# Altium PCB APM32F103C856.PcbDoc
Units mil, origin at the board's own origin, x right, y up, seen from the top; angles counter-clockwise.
Board outline 2110.03 x 910.03 mil, 2 copper layers (Top Layer, Bottom Layer); 23 components, 48 nets, 151 pads, 35 vias.
Unrouted connection lines stored in the file: 7.
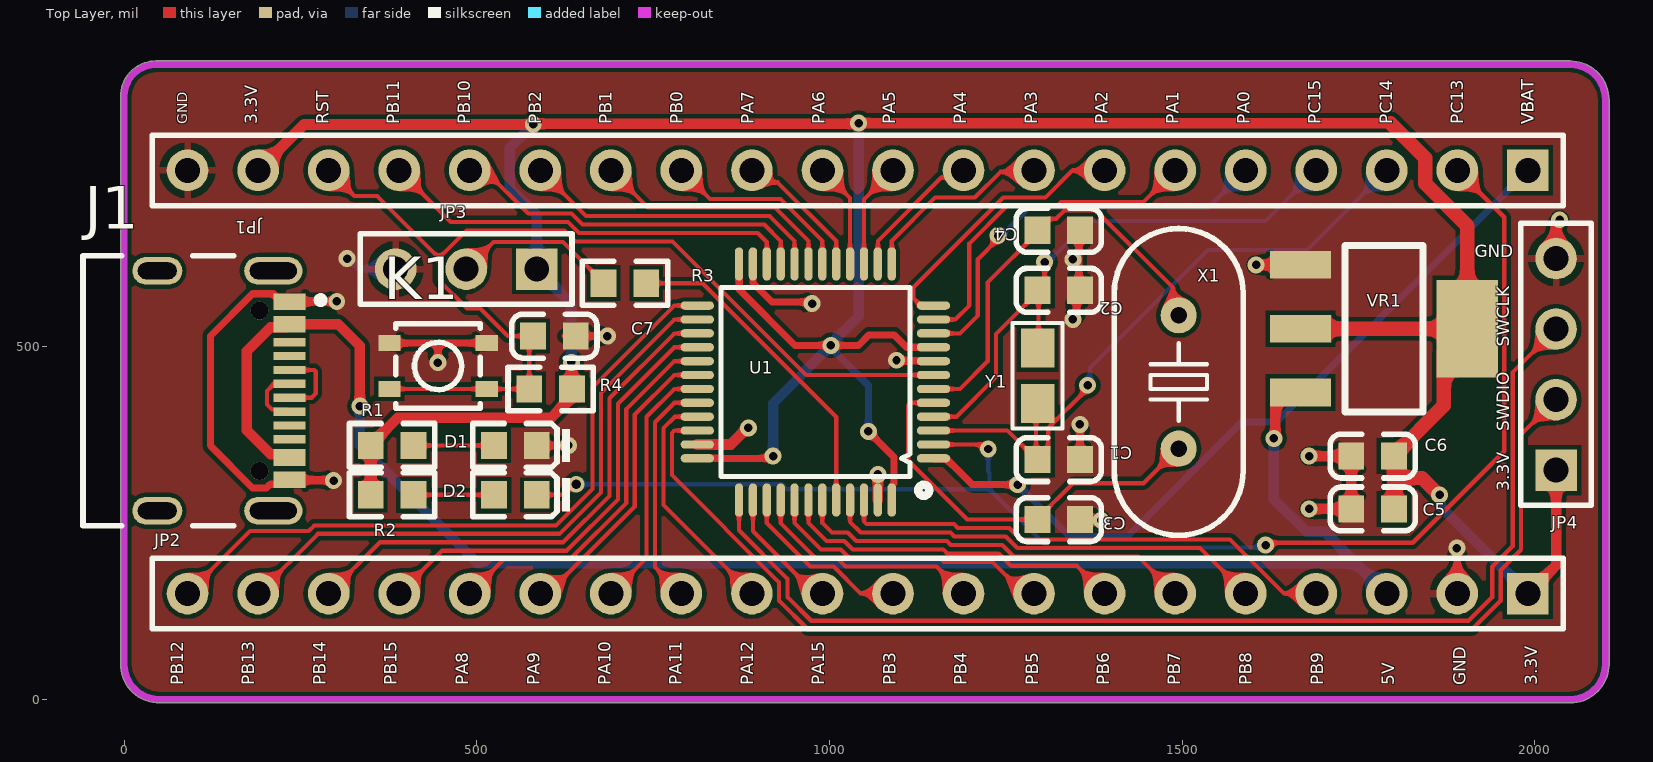
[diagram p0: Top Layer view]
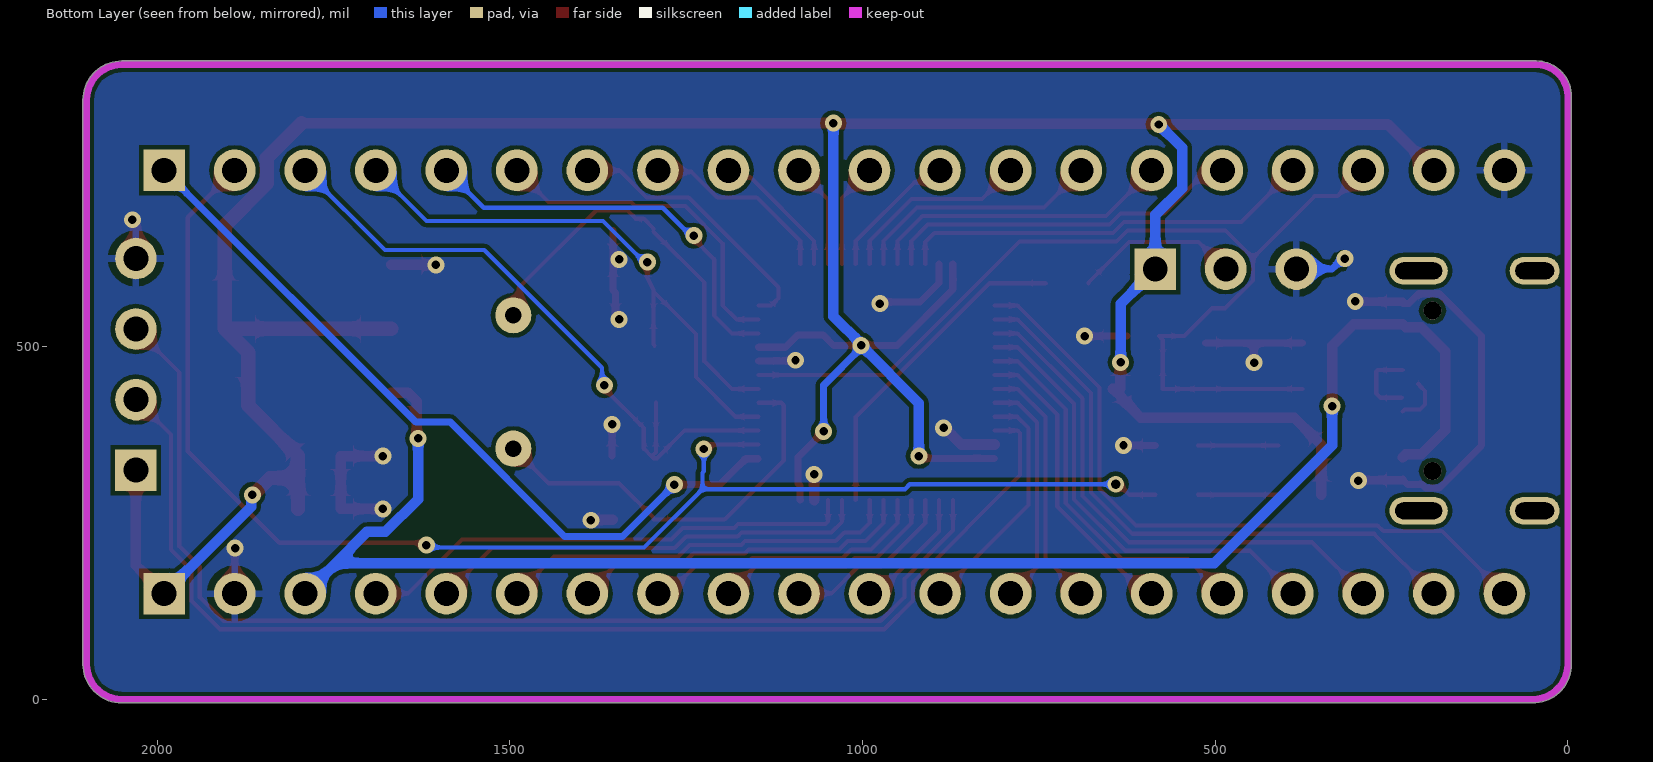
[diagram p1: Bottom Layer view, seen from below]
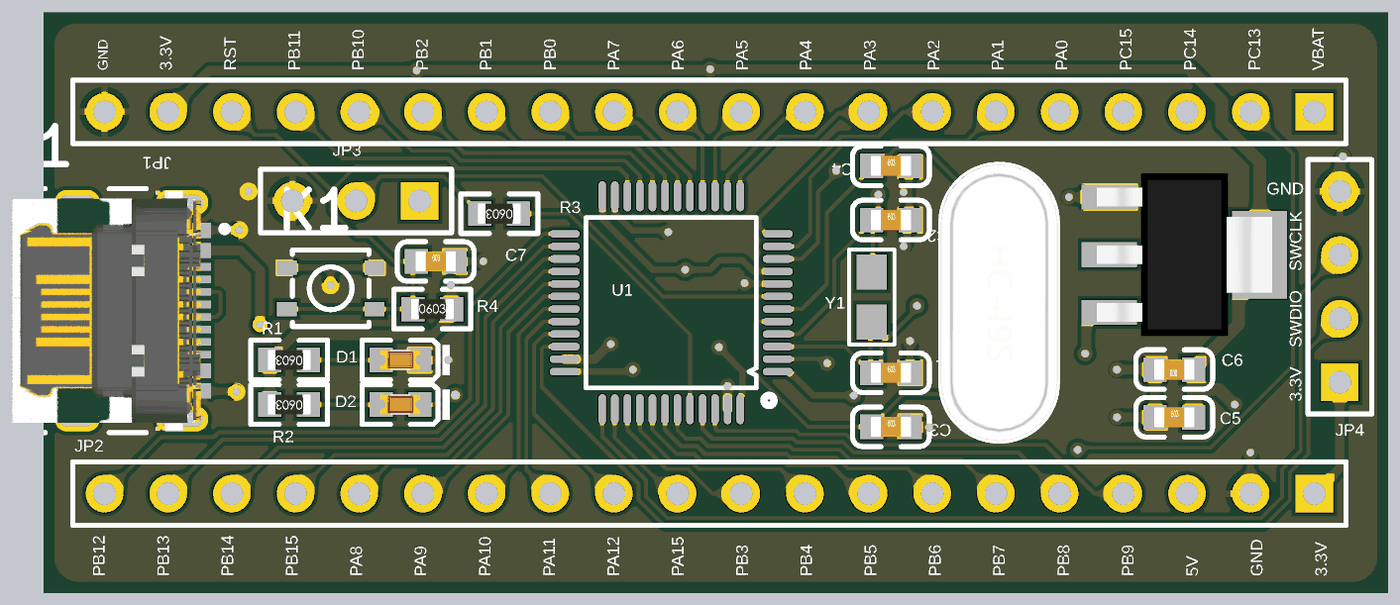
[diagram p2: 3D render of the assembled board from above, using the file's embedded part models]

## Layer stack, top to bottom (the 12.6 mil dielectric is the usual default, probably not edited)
Top Solder: solder mask 0.4, Solder Resist, Dk 3.5
Top Layer: signal copper 1.4
Dielectric 1: dielectric 12.6, FR-4, Dk 4.8
Bottom Layer: signal copper 1.4
Bottom Solder: solder mask 0.4, Solder Resist, Dk 3.5

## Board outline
-5.02,50 -5.02,855 cw(c45,855) 45,905.02 cw(c45,900) 45.04,905.01 2050,905.02 cw(c2050,850) 2105.01,850 2105.01,50 cw(c2050,50) 2050,-5.02 52.5,-5.02 cw(c52.5,0) 52.46,-5.02 50,-5.02 cw(c50,50)

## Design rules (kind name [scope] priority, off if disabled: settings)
Clearance poly [InPolygon] p1: gap=6 ignorepadtopadclearanceinfootprint=TRUE
Clearance [All] p2: gap=6 ignorepadtopadclearanceinfootprint=TRUE
ComponentClearance [All] p1: gap=0 collisioncheckmode=3 verticalgap=0 showdistances=FALSE
HoleToHoleClearance [All] p1: gap=0 allowstackedmicrovias=TRUE
MinimumSolderMaskSliver [All] p1: minsoldermaskwidth=0
PlaneConnect [All] p1: pad.planeconnectstyle=Relief pad.reliefexpansion=20 pad.reliefentries=4 pad.reliefconductorwidth=10 pad.reliefairgap=10 via.planeconnectstyle=Direct via.reliefexpansion=20 via.reliefentries=4 via.reliefconductorwidth=10 via.reliefairgap=10
PolygonConnect [All] p1: thpad.connectstyle=Relief thpad.reliefconductorwidth=10 thpad.reliefentries=4 thpad.polygonreliefangle="90 Angle" thpad.airgapwidth=10 smdpad.connectstyle=Direct smdpad.reliefconductorwidth=10 smdpad.reliefentries=4 smdpad.polygonreliefangle="90 Angle" smdpad.airgapwidth=10 via.connectstyle=Direct via.reliefconductorwidth=10 via.reliefentries=4 via.polygonreliefangle="90 Angle" via.airgapwidth=10
RoutingVias [All] p1: holewidth=12 width=24 viastyle="Through Hole" minholewidth=12 minwidth=24 maxholewidth=12 maxwidth=24
SilkToSilkClearance [All] p1: silktosilkclearance=0
SilkToSolderMaskClearance [IsPad] p1: minsilkscreentomaskgap=0 clearancetoexposedcopper=TRUE
SolderMaskExpansion [All] p1: expansion=2 istentingtop=FALSE useseparateexpansions=TRUE expansionbottom=2 istentingbottom=FALSE
Width Width_1 [InNetClass('POWER')] p1: maxlimit=30 minlimit=10 preferedwidth=15
Width [InNetClass('All Nets')] p2: maxlimit=30 minlimit=6 preferedwidth=6
24 further rules are at their usual default settings.

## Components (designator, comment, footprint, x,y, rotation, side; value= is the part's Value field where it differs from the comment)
C1 "22PF" 0603_C 1325,340 r0 top
C2 "22PF" 0603_C 1325,580 r0 top
C3 "22PF" 0603_C 1325,255 r0 top
C4 "22PF" 0603_C 1325,665 r0 top
C5 "100pF (101) 5% 50V" 0603_C 1770,270 r0 top
C6 "100pF (101) 5% 50V" 0603_C 1770,345 r180 top
C7 "100nF (104) 10% 50V" 0603_C 610,515 r0 top
D1 "红灯 0603" 0603_LED_S1 554.69,360 r180 top
D2 "绿灯 0603" 0603_LED_S1 554.69,290 r180 top
J1 "USB4105-GF-A" FP-USB4105-GF-A-MFG 92.95,437.51 r270 top locked
JP1 "HEADER 20" HDR1X20 1990,750 r180 top locked
JP2 "HEADER 20" HDR1X20 1990,150 r180 top locked
JP3 "HEADER 3" HDR1X3 585,610 r180 top
JP4 "4 HEADER" HDR1X4 2030,325 r90 top
K1 "GT-TS171E-H014-L1" SW-SMD_4P-L3.0-W2.8-P1.65-TL_GT-TS171A-H014-L1 445.13,472.64 r180 top
R1 "4.7KΩ (4701) ±1%" 0603_R 380,360 r180 top
R2 "4.7KΩ (4701) ±1%" 0603_R 380,290 r180 top
R3 "10KΩ (1002) ±1%" 0603_R 710,590 r180 top
R4 "10KΩ (1002) ±1%" 0603_R 604.68,440 r0 top
U1 "IC_APM32F103C8T6_1040100292" LQFP48 980,450 r180 top locked
VR1 "AMS1117-3.3" SOT-223 1786.03,525.5 r180 top
X1 "8MHz" "OSC HC-49S" 1495,450 r270 top
Y1 "CRYSTAL" 3215 1295.01,459.03 r270 top value=32.768KHZ

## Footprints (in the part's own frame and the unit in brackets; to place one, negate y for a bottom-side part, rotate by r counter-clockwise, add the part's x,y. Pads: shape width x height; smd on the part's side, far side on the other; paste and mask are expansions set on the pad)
0603_C [mm]
  rect 0.93x0.98 smd paste+0: 1(-0.77,0)
  rect 0.93x0.98 smd: 2(0.77,0)
  silkscreen extent -1.53,-0.79 1.54,0.79, body extent -0.8,-0.4 0.8,0.4, height 0.3
0603_LED_S1 [mm]
  rect 0.93x0.98 smd: A(0.77,0) K(-0.77,0)
  silkscreen extent -1.98,-0.79 1.54,0.79, body extent -0.8,-0.4 0.8,0.4, height 0.6
0603_R [mm]
  rect 0.93x0.98 smd: 1(-0.77,0) 2(0.77,0)
  silkscreen extent -1.53,-0.79 1.53,0.79, body extent -0.85,-0.4 0.85,0.4, height 0.56
3215 [mm]
  rect 1.4x1.2 smd mask+0.05: 1(-1,0) 2(1,0)
  silkscreen extent -1.9,-0.9 1.9,0.9
FP-USB4105-GF-A-MFG [mm]
  rrect100% 1x2.1 hole 1.7 slot 0.6 at 0 deg paste-1000 mask+0: 1(-4.32,3.015) 2(4.32,3.015)
  rrect100% 1x1.8 hole 1.4 slot 0.6 at 0 deg paste-1000 mask+0: 3(-4.32,-1.165) 4(4.32,-1.165)
  rect 0.6x1.15 smd paste+0 mask+0: A1-B12(-3.2,3.59) A4-B9(-2.4,3.59) B1-A12(3.2,3.59) B4-A9(2.4,3.59)
  rect 0.3x1.15 smd paste+0 mask+0: A5(-1.25,3.59) A6(-0.25,3.59) A7(0.25,3.59) A8(1.25,3.59) B5(1.75,3.59) B6(0.75,3.59) B7(-0.75,3.59) B8(-1.75,3.59)
  round 0.65 hole 0.65 unplated paste-1000 mask+0: ""(-2.89,2.515) ""(2.89,2.515)
  silkscreen extent -4.86,-3.84 4.86,4.84, body extent -4.96,-3.94 4.96,4.27, height 0.25
HDR1X3 [mm] "Connector; Header; 3 Position"
  rect 1.5x1.5 hole 0.9: 1(0,0)
  round 1.5 hole 0.9: 2(2.54,0) 3(5.08,0)
  silkscreen extent -1.27,-1.27 6.35,1.27
HDR1X4 [mm] "Connector; Header; 4 Position"
  rect 1.5x1.5 hole 0.9: 1(0,0)
  round 1.5 hole 0.9: 2(2.54,0) 3(5.08,0) 4(7.62,0)
  silkscreen extent -1.27,-1.27 8.89,1.27
HDR1X20 [mm] "Connector; Header; 20 Position"
  rect 1.5x1.5 hole 0.9: 1(0,0)
  round 1.5 hole 0.9: 2(2.54,0) 3(5.08,0) 4(7.62,0) 5(10.16,0) 6(12.7,0) 7(15.24,0) 8(17.78,0) 9(20.32,0) 10(22.86,0) 11(25.4,0) 12(27.94,0) 13(30.48,0) 14(33.02,0) 15(35.56,0) 16(38.1,0) 17(40.64,0) 18(43.18,0) 19(45.72,0) 20(48.26,0)
  silkscreen extent -1.27,-1.27 49.53,1.27
LQFP48 [mm]
  oval 1.2x0.3 smd: 1(-4.25,2.75) 2(-4.25,2.25) 3(-4.25,1.75) 4(-4.25,1.25) 5(-4.25,0.75) 6(-4.25,0.25) 7(-4.25,-0.25) 8(-4.25,-0.75) 9(-4.25,-1.25) 10(-4.25,-1.75) 11(-4.25,-2.25) 12(-4.25,-2.75) 25(4.25,-2.75) 26(4.25,-2.25) 27(4.25,-1.75) 28(4.25,-1.25) 29(4.25,-0.75) 30(4.25,-0.25) 31(4.25,0.25) 32(4.25,0.75) 33(4.25,1.25) 34(4.25,1.75) 35(4.25,2.25) 36(4.25,2.75)
  oval 0.3x1.2 smd: 13(-2.75,-4.25) 14(-2.25,-4.25) 15(-1.75,-4.25) 16(-1.25,-4.25) 17(-0.75,-4.25) 18(-0.25,-4.25) 19(0.25,-4.25) 20(0.75,-4.25) 21(1.25,-4.25) 22(1.75,-4.25) 23(2.25,-4.25) 24(2.75,-4.25) 37(2.75,4.25) 38(2.25,4.25) 39(1.75,4.25) 40(1.25,4.25) 41(0.75,4.25) 42(0.25,4.25) 43(-0.25,4.25) 44(-0.75,4.25) 45(-1.25,4.25) 46(-1.75,4.25) 47(-2.25,4.25) 48(-2.75,4.25)
  silkscreen extent -4.1,-3.4 3.4,4.1
"OSC HC-49S" [mm] "SMD, 2-Leads, Body 5x11.7mm"
  round 1.3 hole 0.6: 1(-2.4,0) 2(2.4,0)
  silkscreen extent -5.52,-2.32 5.52,2.33, body extent -5.52,-2.32 5.53,2.33, height 4.13
SOT-223 [mm]
  rect 2.2x1 smd: 1(3,-2.3) 2(3,0) 3(3,2.3)
  rect 2.2x3.5 smd: 2(-3,0)
  silkscreen extent -1.4,-3 1.4,3, body extent -3.49,-3.24 3.49,3.24, height 1.64
SW-SMD_4P-L3.0-W2.8-P1.65-TL_GT-TS171A-H014-L1 [mm]
  rect 0.8x0.575 smd: 1(-1.75,0.825) 2(-1.75,-0.825) 3(1.75,0.825) 4(1.75,-0.825)
  silkscreen extent -1.52,-1.52 1.52,1.52

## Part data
C1 C2 C3 C4 C5 C6: library part "0603 100pF (101) 5% 50V", "贴片电容", Package=0603, SuppliersPartNumber=C14858
C7: library part "0603 100nF (104) 10% 50V", "贴片电容", Package=0603, SuppliersPartNumber=C14663
D1: library part "0603 红灯", "发光二极管", Package=0603, SuppliersPartNumber=C2286
D2: library part "0603 绿灯", "发光二极管", Package=0603, SuppliersPartNumber=C72043
J1: library part CMP-245163-000001-1, "CONN RCPT USB2.0 TYPEC 5A", Current Rating=5/6.25/1.25/0.25A, Manufacturer=GCT, Package=0, Temperature="-40°C to +85°C", Temperature Range High=+85°C, Temperature Range Low=-40°C, Voltage Rating=20V
JP4: "4 Pin Header"
K1: BOM_JLCPCB Part Class="Extended Part", BOM_Manufacturer=G-Switch
R1 R2: library part "0603 4.7KΩ (4701) 1%", "贴片电阻", Package=0603, SuppliersPartNumber=C23162
R3 R4: library part "0603 10KΩ (1002) 1%", "贴片电阻", Package=0603, SuppliersPartNumber=C25804
VR1: library part "SOT-223 AMS1117-3.3", "低压差线性稳压(LDO)", Package=SOT-223, SuppliersPartNumber=C6186
X1: library part XTAL-2P, "2脚无源脚晶振"
Y1: "XTAL 32.768KHZ 7PF 20PPM -- SMT"

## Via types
v1: diameter 24, hole 12, Top Layer to Bottom Layer, tented both sides, 29 vias
v2: diameter 24, hole 12, Top Layer to Bottom Layer, 5 vias
v3: diameter 24, hole 14, Top Layer to Bottom Layer, tented both sides, 1 vias

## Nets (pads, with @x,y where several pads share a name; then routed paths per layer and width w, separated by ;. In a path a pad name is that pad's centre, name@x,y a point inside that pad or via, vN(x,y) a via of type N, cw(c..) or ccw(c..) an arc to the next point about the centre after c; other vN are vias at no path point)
BOOT0: R3.1 U1.44 | length 465.4
  Top Layer w6: R3.1 819.75,590 1009.53,400.22 U1.44
DN: J1.A7 J1.B7 | length 108.3
  Top Layer w6: J1.B7 269.64,467.03 271.8,464.87 271.8,433.59 265.92,427.71 J1.A7@235.6,427.71
DP: J1.A6 J1.B6 | length 69.1
  Top Layer w6: J1.A6@212.59,447.18 212.53,447.18 202.65,437.3 202.65,418.03 209.79,410.88 231.38,410.88 J1.B6
GND: C1.2 C2.2 C3.2 C4.2 C5.1 C6.2 C7.2 D1.K J1.A1-B12 J1.B1-A12 JP1.20 JP2.2 JP3.3 JP4.4 K1.2 K1.4 U1.8 U1.23 U1.35 U1.47 VR1.1 | length 1799.1
  Top Layer w10: J1.A1-B12@233.67,561.4 225.55,561.4 211.87,575.08 182.11,575.08 122.4,515.38 122.4,359.63 182.11,299.93 201.82,299.93 206.6,304.71 227.47,304.71 J1.B1-A12 ; K1.4 445.13,505.12 ; v2(444.93,477.36) 445.13,477.56 445.13,505.12 ; K1.2 445.13,505.12 ; D1.K v1(630,360) ; C7.2@625.32,515 v1(685,515) ; U1.23 891.77,616.97 891.77,590.2 918.47,563.5 972.87,563.5 v1(975.27,561.09) ; v1(1095,480.84) 1095.96,479.88 1146.97,479.88 U1.8 ; v1(1345,538.66) 1346.59,538.66 1350.37,542.44 1350.37,576.82 1353.54,580 v1@1353.54,623.66 ; v1(1345,623.66) v1@1353.54,623.66 ; C4.2@1353.54,665 v1@1353.54,623.66 ; C1.2@1355,345 v1(1355,390) ; v1(1889.47,214.47) 1889.73,214.2 1889.73,150.27 JP2.2
  Top Layer w12: J1.B1-A12 235.02,310.79 296.41,310.79 v2(297.15,310.05) ; J1.A1-B12 234.71,563.91 296.9,563.91 v2@297.73,564.74
  Top Layer w15: U1.35 859.79,361.42 883.37,385 v1(885,385) ; U1.47 U1.47 1068.64,318.94 v1(1068.69,319) ; C3.2@1354.04,254.5 1384.5,254.5 v1(1385,254) ; v1(1604.66,616.05) VR1.1 ; v1(1680,270) C5.1 C6.2 v1(1680,345) ; JP4.4 2030,672.56 2035,677.56 v1(2035,680)
  Bottom Layer w10: v2@318.21,626.1 318.7,626.1 334.44,610.36 384.64,610.36 JP3.3
  other v2: 301.45,564.33 316.15,624.86
NetC3_1: C3.1 U1.5 X1.2 | length 574.7
  Top Layer w6: U1.5 1115.18,420.47 1111.67,416.96 1111.67,338.59 1195.25,255 C3.1@1296.46,255 ; C3.1@1296.46,256.97 1296.46,257.76 1345.19,306.49 1445.08,306.49 1494.11,355.51 X1.2
NetC4_1: C4.1 U1.6 X1.1 | length 596.6
  Top Layer w6: U1.6 1184.99,440.16 1224.2,479.37 1224.2,590.86 1296.37,663.03 C4.1@1296.46,663.03 ; C4.1@1296.46,666.97 1296.46,667.76 1309.99,681.29 1321.28,681.29 1333.28,693.29 1377.35,693.29 1486.84,583.8 1486.84,552.65 X1.1
NetD1_A: D1.A R1.1 | length 114.1
  Top Layer w6: R1.1 D1.A
NetD2_A: D2.A R2.1 | length 114.1
  Top Layer w6: R2.1 D2.A
NetJP3_2: JP3.2 R3.2 | length 235.5
  Top Layer w6: JP3.2 523.53,648.53 622.14,648.53 679.68,590.98 R3.2
PA0: JP1.5 U1.10 | length 593.2
  Top Layer w6: U1.10 1184.99,518.9 1210.26,544.17 1210.26,624.05 1238.97,652.76 v1(1238.97,657.5)
  Bottom Layer w6: v1@1235.25,653.78 1239.99,653.78 1283.15,696.94 1536.94,696.94 JP1.5
PA1: JP1.6 U1.11 | length 481.7
  Top Layer w6: U1.11 1178.18,538.58 1198.26,558.66 1198.26,646.49 1251.24,699.47 1322.49,699.47 1328.31,705.29 1445.29,705.29 JP1.6
PA2: JP1.7 U1.12 | length 387.7
  Top Layer w6: U1.12 1129.6,558.27 1119.06,568.81 1119.06,584.27 1246.27,711.47 1305.96,711.47 1344.12,749.63 1389.63,749.63 JP1.7
PA3: JP1.8 U1.13 | length 275.8
  Top Layer w6: U1.13 1088.27,649.94 1149.8,711.47 1205.96,711.47 1242.4,747.91 1287.91,747.91 JP1.8
PA4: JP1.9 U1.14 | length 195.5
  Top Layer w6: U1.14 1068.58,649.94 1158.49,739.85 1179.85,739.85 JP1.9
PA5: JP1.10 U1.15 | length 149.7
  Top Layer w6: U1.15 1048.9,708.9 JP1.10
PA6: JP1.11 U1.16 | length 148.9
  Top Layer w6: JP1.11 1029.21,710.79 U1.16
PA7: JP1.12 U1.17 | length 193.6
  Top Layer w6: JP1.12 907.02,732.98 926.49,732.98 1009.53,649.94 U1.17
PA8: JP2.16 U1.29 | length 537.1
  Top Layer w6: JP2.16 538.71,198.71 632.29,198.71 712,278.42 712,411.47 780.06,479.53 U1.29
PA9: JP2.15 U1.30 | length 427.4
  Top Layer w6: JP2.15 600.55,150 724,273.45 724,403.78 780.06,459.84 U1.30
PA10: JP2.14 U1.31 | length 360.1
  Top Layer w6: JP2.14 740.54,200.54 740.54,400.65 780.06,440.16 U1.31
PA11: JP2.13 U1.32 | length 330
  Top Layer w6: JP2.13 752.54,187.46 752.54,392.96 780.06,420.47 U1.32
PA12: JP2.12 U1.33 | length 341.4
  Top Layer w6: U1.33 780.79,400.79 764.54,384.54 764.54,275.46 JP2.12
PA15: JP2.11 U1.38 | length 179.5
  Top Layer w6: U1.38 891.42,238.3 979.72,150 JP2.11
PB0: JP1.13 U1.18 | length 273.9
  Top Layer w6: JP1.13 830.75,709.25 930.53,709.25 989.84,649.94 U1.18
PB1: JP1.14 U1.19 | length 354.2
  Top Layer w6: JP1.14 742.75,697.25 922.85,697.25 970.16,649.94 U1.19
PB2: JP1.15 U1.20 | length 434.5
  Top Layer w6: JP1.15 654.75,685.25 915.16,685.25 950.47,649.94 U1.20
PB3: JP2.10 U1.39 | length 253
  Top Layer w6: U1.39 911.1,250.06 972.63,188.53 1005.96,188.53 1044.12,150.37 1089.63,150.37 JP2.10
PB4: JP2.9 U1.40 | length 333.3
  Top Layer w6: U1.40 930.79,250.06 980.32,200.53 1010.93,200.53 1022.93,188.53 1151.47,188.53 JP2.9
PB5: JP2.8 U1.41 | length 413.6
  Top Layer w6: U1.41 950.47,250.06 988,212.53 1015.9,212.53 1027.9,200.53 1156.44,200.53 1161.97,195 1230.85,195 1275.85,150 JP2.8
PB6: JP2.7 U1.42 | length 493.9
  Top Layer w6: U1.42 970.16,250.06 995.69,224.53 1020.87,224.53 1032.87,212.53 1161.41,212.53 1166.94,207 1239.99,207 1257.66,189.33 1350.67,189.33 JP2.7
PB7: JP2.6 U1.43 | length 574.2
  Top Layer w6: U1.43 989.84,250.06 1003.37,236.53 1025.84,236.53 1037.84,224.53 1166.38,224.53 1171.91,219 1244.96,219 1261.25,202.71 1437.29,202.71 JP2.6
PB8: JP2.5 U1.45 | length 633.9
  Top Layer w6: U1.45 1029.21,251.71 1044.39,236.53 1171.35,236.53 1176.88,231 1249.93,231 1266.22,214.71 1525.29,214.71 JP2.5
PB9: JP2.4 U1.46 | length 714
  Top Layer w6: U1.46 1048.9,252.04 1052.41,248.53 1176.32,248.53 1181.85,243 1254.9,243 1271.19,226.71 1567.78,226.71 1644.12,150.37 1689.63,150.37 JP2.4
PB10: JP1.16 U1.21 | length 514.9
  Top Layer w6: JP1.16 511.85,750 573.03,688.82 634.21,688.82 649.78,673.25 907.48,673.25 930.79,649.94 U1.21
PB11: JP1.17 U1.22 | length 594.3
  Top Layer w6: JP1.17 463.18,676.82 629.24,676.82 644.81,661.25 898.24,661.25 911.1,648.39 U1.22
PB12: JP2.20 U1.25 | length 976.1
  Top Layer w6: JP2.20 178.74,238.74 261.77,238.74 269.74,246.71 612.41,246.71 664,298.3 664,442.21 780.06,558.27 U1.25
PB13: JP2.19 U1.26 | length 866.3
  Top Layer w6: JP2.19 274.71,234.71 617.38,234.71 676,293.33 676,434.52 780.06,538.58 U1.26
PB14: JP2.18 U1.27 | length 756.6
  Top Layer w6: JP2.18 362.71,222.71 622.35,222.71 688,288.36 688,426.84 780.06,518.9 U1.27
PB15: JP2.17 U1.28 | length 646.9
  Top Layer w6: JP2.17 450.71,210.71 627.32,210.71 700,283.39 700,419.15 780.06,499.21 U1.28
PC13: D2.K JP1.2 U1.2 | length 2034.9
  Top Layer w6: D2.K 621.26,290 636.26,305 v3(641,305) ; U1.2 1218.51,361.42 v1@1224.79,355.14 ; v1(1618.28,218.8) 1621.63,222.15 1826.85,222.15 1956.45,351.75 1956.45,683.55 JP1.2
  Bottom Layer w6: v3(641,305) 932.94,305 939.94,298 1227,298 ; v1(1225,355) 1225,323.34 1227,321.34 1227,298 ; v1(1618.28,218.8) 1614.92,215.44 1309.56,215.44 1227,298
PC14: C1.1 JP1.3 U1.3 Y1.2 | length 939.3
  Top Layer w6: U1.3 1252.14,381.1 1291.27,341.97 1296.46,341.97 C1.1@1298.96,344.47 ; Y1.2@1292.91,421 1292.91,350.51 C1.1@1298.96,344.47 ; v1(1366,445.38) 1366,440.64 1309.99,384.63 1309.99,355.5 C1.1@1298.96,344.47
  Bottom Layer w6: v1(1366,445.38) 1369.35,448.73 1369.35,470.11 1536.29,637.05 1677.05,637.05 JP1.3
PC15: C2.1 JP1.4 U1.4 Y1.1 | length 818.2
  Top Layer w6: U1.4 1179.94,400.79 1236.2,457.04 1236.2,517.86 1296.46,578.12 1296.46,580 1305,597.67 v1(1305,620) ; Y1.1@1294.69,501.51 1296.46,503.28 C2.1@1296.46,578.03
  Bottom Layer w6: v1(1305,620) 1309.74,620 1367.93,678.18 1618.18,678.18 JP1.4
RST: C7.1 JP1.18 K1.1 K1.3 R4.1 U1.7 | length 1483
  Top Layer w6: JP1.18 326.34,713.66 358.77,713.66 446.47,625.96 ; K1.3 K1.1 514.18,440 R4.1 574.37,509.68 C7.1 543.94,515 504.42,554.52 485.99,554.52 446.47,594.04 446.47,625.96 ; U1.7 966.88,459.84 777.46,649.25 639.84,649.25 624.27,664.82 485.33,664.82 446.47,625.96
SWCLK: JP4.3 U1.37 | length 1610.4
  Top Layer w6: U1.37 871.73,239.73 940.53,170.93 940.53,144.99 974.04,111.47 1905.96,111.47 1939.47,144.99 1939.47,188.23 1968.45,217.2 1968.45,463.45 JP4.3
SWDIO: JP4.2 U1.34 | length 1712.2
  Top Layer w6: U1.34 780.06,381.1 776.54,377.59 776.54,317.94 928.53,165.96 928.53,140.02 969.07,99.47 1910.93,99.47 1951.47,140.02 1951.47,183.26 1980.45,212.23 1980.45,375.45 JP4.2
VBAT: JP1.1 U1.1 | length 1102.7
  Top Layer w10: U1.1@1147.91,341.14 1165.63,341.14 1202.35,304.42 v1(1266.6,304.42)
  Bottom Layer w10: v1(1266.6,304.42) 1340.02,231 1422.23,231 1584.23,393 1633,393 JP1.1
VCC_3.3V: C5.2 C6.1 JP1.19 JP2.1 JP3.1 JP4.1 R1.2 R2.2 R4.2 U1.9 U1.24 U1.36 U1.48 VR1.2 | length 5034.3
  Top Layer w10: U1.36 912.94,341.73 916.21,345 v1(920,345) ; U1.24 872.08,616.97 872.08,581.18 951.33,501.92 v1(1001.92,501.92) 1041.11,501.92 1056.06,516.87 1091.47,516.87 1109.13,499.21 U1.9 ; v1(1055,380) 1091.69,343.31 1091.69,306.12 1088.62,303.05 1088.62,283.03 U1.48
  Top Layer w15: JP1.19 255,815 v1(580,815) 581.02,816.02 1040.22,816.02 v1(1041.24,817.04) 1795,817.04 ; R2.2 349.68,360.98 387.83,399.13 605.33,399.13 632.67,426.48 632.67,428.21 644.46,440 R4.2@645.32,440 ; v1(634.03,477.71) 634.51,477.22 634.51,440.49 R4.2 ; JP2.1 2030,190 JP4.1
  Top Layer w20: VR1.2@1667.92,525.5 VR1.2@1904.14,525.5 ; 1795,817.04 1844.47,767.57 1844.47,731.14 1904.14,671.48 VR1.2@1904.14,525.5 ; C5.2 1800.32,313.9 ; v1(1865,290) 1863.92,290 1840.02,313.9 1800.32,313.9 ; 1800.32,313.9 C6.1 1800.32,345.98 1870.83,416.5 1870.83,492.19 VR1.2@1904.14,525.5
  Bottom Layer w10: v1(1001.92,501.92) 1001.92,498.48 1055,445.4 v1(1055,380)
  Bottom Layer w15: v1(580,815) 546.97,781.97 546.97,724.8 585,686.77 JP3.1 634.03,560.97 v1(634.03,477.71) ; v1(920,345) 920,420 v1(1001.92,501.92) 1001.92,504.04 1041.24,543.36 v1(1041.24,817.04) ; v1(1865,290) 1866.72,288.28 1866.72,273.28 JP2.1
VCC_5V: J1.A4-B9 J1.B4-A9 JP2.3 VR1.3 | length 2396.8
  Top Layer w15: J1.B4-A9 229.97,347.33 207.93,347.33 173.65,381.6 173.65,493.41 207.93,527.68 229.97,527.68 J1.A4-B9 260.64,531.99 303.36,531.99 334.2,501.16 v2(334.2,415.64) ; v1(1630,370) 1630,372.44 1632.11,374.55 1632.11,422.76 1644.3,434.94 VR1.3
  Bottom Layer w15: v2(334.2,415.64) 334.2,360.15 501.32,193.03 1746.97,193.03 ; v1(1630,370) 1630,283.94 1676.32,237.62 1702.38,237.62 1746.97,193.03 ; JP2.3 1746.97,193.03
pads on no net: J1. J1.1 J1.2 J1.3 J1.4 J1.A5 J1.A8 J1.B5 J1.B8

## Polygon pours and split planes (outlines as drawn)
GND on Top Layer "GND_L01_P000" (solid, remove dead copper, pour order 0): -5.02,50 -5.02,855 cw(c45,855) 45,905.02 cw(c45,900) 45.04,905.01 2050,905.02 cw(c2050,850) 2105.01,850 2105.01,50 cw(c2050,50) 2050,-5.02 52.5,-5.02 cw(c52.5,0) 52.46,-5.02 50,-5.02 cw(c50,50)
GND on Bottom Layer "GND_L02_P001" (solid, remove dead copper, pour order 1): -5.02,50 -5.02,855 cw(c45,855) 45,905.02 cw(c45,900) 45.04,905.01 2050,905.02 cw(c2050,850) 2105.01,850 2105.01,50 cw(c2050,50) 2050,-5.02 52.5,-5.02 cw(c52.5,0) 52.46,-5.02 50,-5.02 cw(c50,50)

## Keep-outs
Keep-Out Layer:
  lines w10: 52.5,0 2050,0 ; 75,0 50,0 ; 100,0 50,0 ; 1935,0 2050,0 ; 2100,485 2100,850 ccw(c2050,850) 2050,900 45,900 ccw(c45,855) 0,855 0,50 ccw(c50,50) 50,0 ; 2100,575 2100,50 cw(c2050,50) 2050,0

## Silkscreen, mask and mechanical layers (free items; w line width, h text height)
Top Overlay:
  text "GND" at 94.72,815 h25 r90
  text "3.3V" at 195.37,815 h30 r90
  text "RST" at 296.26,815 h30 r90
  text "PB11" at 396.58,815 h30 r90
  text "PB10" at 497.22,815 h30 r90
  text "PB2" at 597.54,815 h30 r90
  text "PB1" at 697.85,815 h30 r90
  text "PB0" at 798.5,815 h30 r90
  text "PA7" at 898.73,815 h30 r90
  text "PA6" at 999.37,815 h30 r90
  text "PA5" at 1099.93,815 h30 r90
  text "PA4" at 1200.16,815 h30 r90
  text "PA3" at 1300.81,815 h30 r90
  text "PA2" at 1401.12,815 h30 r90
  text "PA1" at 1501.44,815 h30 r90
  text "PA0" at 1602.08,815 h30 r90
  text "PC15" at 1702.98,815 h30 r90
  text "PC14" at 1803.87,815 h30 r90
  text "PC13" at 1904.77,815 h30 r90
  text "VBAT" at 2005,815.03 h30 r90
  text "VBAT" at 2005,815.03 h30 r90
  text "GND" at 1915,620.33 h30
  text "SWCLK" at 1969.67,500 h30 r90
  text "SWDIO" at 1969.67,380 h30 r90
  text "3.3V" at 1969.67,295 h30 r90
  text "PB12" at 90,20 h30 r90
  text "PB13" at 191.13,20 h30 r90
  text "PB14" at 291.92,20 h30 r90
  text "PB15" at 393.05,20 h30 r90
  text "PA8" at 494.18,20 h30 r90
  text "PA9" at 595.3,20 h30 r90
  text "PA10" at 696.43,20 h30 r90
  text "PA11" at 797.22,20 h30 r90
  text "PA12" at 898.02,20 h30 r90
  text "PA15" at 999.14,20 h30 r90
  text "PB3" at 1100.27,20 h30 r90
  text "PB4" at 1200.98,20 h30 r90
  text "PB5" at 1302.03,20 h30 r90
  text "PB6" at 1403.15,20 h30 r90
  text "PB7" at 1503.87,20 h30 r90
  text "PB8" at 1604.99,20 h30 r90
  text "PB9" at 1706.12,20 h30 r90
  text "5V" at 1807.16,20 h30 r90
  text "GND" at 1908.54,20 h30 r90
  text "3.3V" at 2009.67,20 h30 r90

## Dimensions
-115,900 to -30,750 on Mechanical 13
-150,900 to -110,750 on Mechanical 13
-200,0 to -100,150 on Mechanical 13
-35,0 to -115,900 on Mechanical 13
0,-20 to 2100,-80 on Mechanical 13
